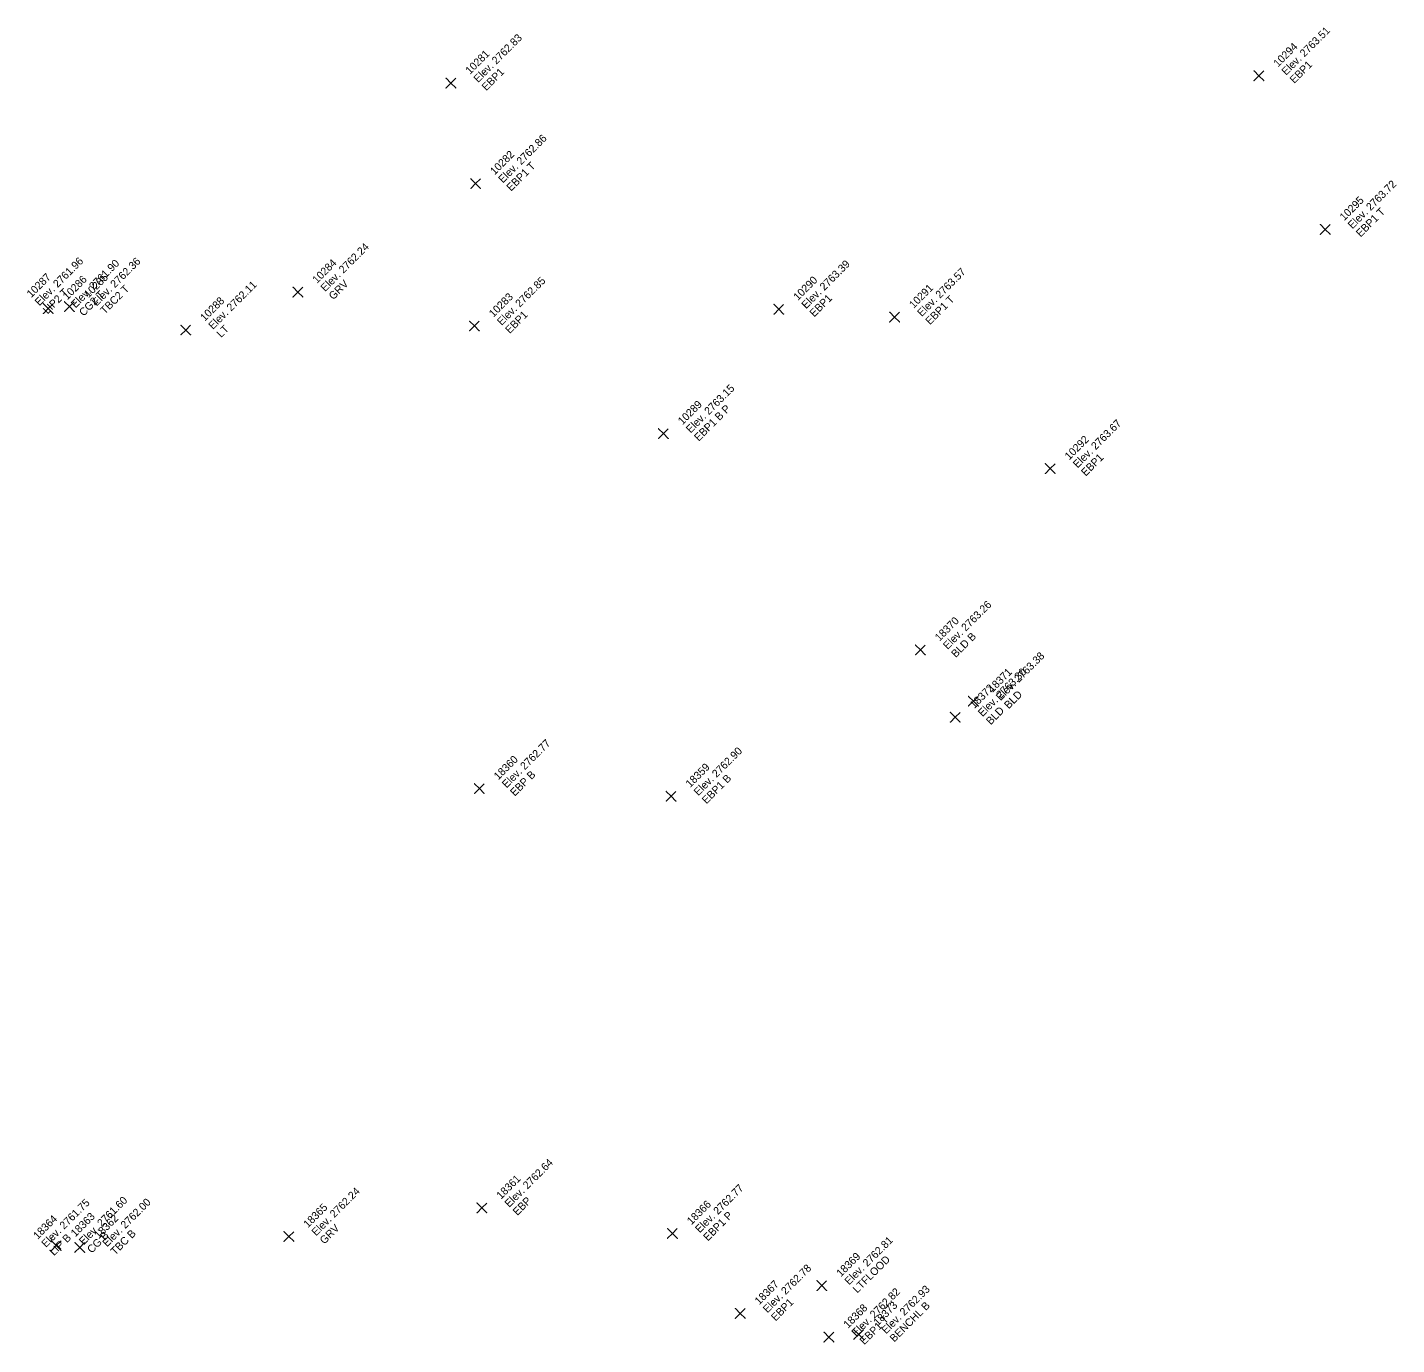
# Model space of a CAD drawing. Extents: x 2493999 to 2503109, y 700767 to 706646.
# Drawn here: x 2502305.4 to 2502348.06, y 701232.19 to 701273.23 of the extents above; entities that cross this region are included whole.
import ezdxf

# ---------------------------------------------------------------- set-up
doc = ezdxf.new("R2010")
doc.units = 0
doc.layers.add('ALG_CL_BLUE_Horiz', color=7, linetype='Continuous')
doc.layers.add('DES_SURFACE_Existing-Ground', color=7, linetype='Continuous')

msp = doc.modelspace()

# ---------------------------------------------------------------- linework, layer by layer
at = {"layer": 'ALG_CL_BLUE_Horiz'}
for points in [[(2502343.772, 701271.726), (2502343.622, 701271.876), (2502343.772, 701271.726), (2502343.622, 701271.576), (2502343.772, 701271.726), (2502343.922, 701271.576), (2502343.772, 701271.726), (2502343.922, 701271.876)], [(2502318.599, 701271.499), (2502318.449, 701271.649), (2502318.599, 701271.499), (2502318.449, 701271.349), (2502318.599, 701271.499), (2502318.749, 701271.349), (2502318.599, 701271.499), (2502318.749, 701271.649)], [(2502319.37, 701268.366), (2502319.22, 701268.516), (2502319.37, 701268.366), (2502319.22, 701268.216), (2502319.37, 701268.366), (2502319.52, 701268.216), (2502319.37, 701268.366), (2502319.52, 701268.516)], [(2502345.837, 701266.939), (2502345.687, 701267.089), (2502345.837, 701266.939), (2502345.687, 701266.789), (2502345.837, 701266.939), (2502345.987, 701266.789), (2502345.837, 701266.939), (2502345.987, 701267.089)], [(2502313.833, 701264.985), (2502313.683, 701265.135), (2502313.833, 701264.985), (2502313.683, 701264.835), (2502313.833, 701264.985), (2502313.983, 701264.835), (2502313.833, 701264.985), (2502313.983, 701265.135)], [(2502306.054, 701264.473), (2502305.904, 701264.623), (2502306.054, 701264.473), (2502305.904, 701264.323), (2502306.054, 701264.473), (2502306.204, 701264.323), (2502306.054, 701264.473), (2502306.204, 701264.623)], [(2502306.715, 701264.534), (2502306.565, 701264.684), (2502306.715, 701264.534), (2502306.565, 701264.384), (2502306.715, 701264.534), (2502306.865, 701264.384), (2502306.715, 701264.534), (2502306.865, 701264.684)], [(2502328.815, 701264.451), (2502328.665, 701264.601), (2502328.815, 701264.451), (2502328.665, 701264.301), (2502328.815, 701264.451), (2502328.965, 701264.301), (2502328.815, 701264.451), (2502328.965, 701264.601)], [(2502332.421, 701264.206), (2502332.271, 701264.356), (2502332.421, 701264.206), (2502332.271, 701264.056), (2502332.421, 701264.206), (2502332.571, 701264.056), (2502332.421, 701264.206), (2502332.571, 701264.356)], [(2502310.337, 701263.805), (2502310.187, 701263.955), (2502310.337, 701263.805), (2502310.187, 701263.655), (2502310.337, 701263.805), (2502310.487, 701263.655), (2502310.337, 701263.805), (2502310.487, 701263.955)], [(2502319.331, 701263.93), (2502319.181, 701264.08), (2502319.331, 701263.93), (2502319.181, 701263.78), (2502319.331, 701263.93), (2502319.481, 701263.78), (2502319.331, 701263.93), (2502319.481, 701264.08)], [(2502325.219, 701260.578), (2502325.069, 701260.728), (2502325.219, 701260.578), (2502325.069, 701260.428), (2502325.219, 701260.578), (2502325.369, 701260.428), (2502325.219, 701260.578), (2502325.369, 701260.728)], [(2502337.27, 701259.486), (2502337.12, 701259.636), (2502337.27, 701259.486), (2502337.12, 701259.336), (2502337.27, 701259.486), (2502337.42, 701259.336), (2502337.27, 701259.486), (2502337.42, 701259.636)], [(2502333.225, 701253.836), (2502333.075, 701253.986), (2502333.225, 701253.836), (2502333.075, 701253.686), (2502333.225, 701253.836), (2502333.375, 701253.686), (2502333.225, 701253.836), (2502333.375, 701253.986)], [(2502334.876, 701252.24), (2502334.726, 701252.39), (2502334.876, 701252.24), (2502334.726, 701252.09), (2502334.876, 701252.24), (2502335.026, 701252.09), (2502334.876, 701252.24), (2502335.026, 701252.39)], [(2502334.312, 701251.741), (2502334.162, 701251.891), (2502334.312, 701251.741), (2502334.162, 701251.591), (2502334.312, 701251.741), (2502334.462, 701251.591), (2502334.312, 701251.741), (2502334.462, 701251.891)], [(2502319.485, 701249.516), (2502319.335, 701249.666), (2502319.485, 701249.516), (2502319.335, 701249.366), (2502319.485, 701249.516), (2502319.635, 701249.366), (2502319.485, 701249.516), (2502319.635, 701249.666)], [(2502325.459, 701249.277), (2502325.309, 701249.427), (2502325.459, 701249.277), (2502325.309, 701249.127), (2502325.459, 701249.277), (2502325.609, 701249.127), (2502325.459, 701249.277), (2502325.609, 701249.427)], [(2502319.566, 701236.451), (2502319.416, 701236.601), (2502319.566, 701236.451), (2502319.416, 701236.301), (2502319.566, 701236.451), (2502319.716, 701236.301), (2502319.566, 701236.451), (2502319.716, 701236.601)], [(2502313.552, 701235.56), (2502313.402, 701235.71), (2502313.552, 701235.56), (2502313.402, 701235.41), (2502313.552, 701235.56), (2502313.702, 701235.41), (2502313.552, 701235.56), (2502313.702, 701235.71)], [(2502325.501, 701235.654), (2502325.351, 701235.804), (2502325.501, 701235.654), (2502325.351, 701235.504), (2502325.501, 701235.654), (2502325.651, 701235.504), (2502325.501, 701235.654), (2502325.651, 701235.804)], [(2502306.305, 701235.276), (2502306.155, 701235.426), (2502306.305, 701235.276), (2502306.155, 701235.126), (2502306.305, 701235.276), (2502306.455, 701235.126), (2502306.305, 701235.276), (2502306.455, 701235.426)], [(2502307.035, 701235.219), (2502306.885, 701235.369), (2502307.035, 701235.219), (2502306.885, 701235.069), (2502307.035, 701235.219), (2502307.185, 701235.069), (2502307.035, 701235.219), (2502307.185, 701235.369)], [(2502330.155, 701234.031), (2502330.005, 701234.181), (2502330.155, 701234.031), (2502330.005, 701233.881), (2502330.155, 701234.031), (2502330.305, 701233.881), (2502330.155, 701234.031), (2502330.305, 701234.181)], [(2502327.612, 701233.162), (2502327.462, 701233.312), (2502327.612, 701233.162), (2502327.462, 701233.012), (2502327.612, 701233.162), (2502327.762, 701233.012), (2502327.612, 701233.162), (2502327.762, 701233.312)], [(2502330.376, 701232.427), (2502330.226, 701232.577), (2502330.376, 701232.427), (2502330.226, 701232.277), (2502330.376, 701232.427), (2502330.526, 701232.277), (2502330.376, 701232.427), (2502330.526, 701232.577)], [(2502331.307, 701232.506), (2502331.157, 701232.656), (2502331.307, 701232.506), (2502331.157, 701232.356), (2502331.307, 701232.506), (2502331.457, 701232.356), (2502331.307, 701232.506), (2502331.457, 701232.656)]]:
    msp.add_lwpolyline(points, dxfattribs=at)

# ---------------------------------------------------------------- texts
at = {"layer": 'DES_SURFACE_Existing-Ground'}
for s, p in [('Elev. 2763.51', (2502344.621, 701271.726)), ('Elev. 2762.83', (2502319.448, 701271.499)), ('10294', (2502344.366, 701271.981)), ('10281', (2502319.193, 701271.754)), ('EBP1', (2502319.702, 701271.244)), ('EBP1', (2502344.875, 701271.471)), ('Elev. 2762.86', (2502320.219, 701268.366)), ('10282', (2502319.964, 701268.621)), ('EBP1 T', (2502320.473, 701268.111)), ('Elev. 2763.72', (2502346.686, 701266.939)), ('10295', (2502346.431, 701267.194)), ('EBP1 T', (2502346.94, 701266.684)), ('Elev. 2762.24', (2502314.682, 701264.985)), ('Elev. 2761.96', (2502305.78, 701264.542)), ('Elev. 2761.90', (2502306.903, 701264.473)), ('Elev. 2762.36', (2502307.564, 701264.534)), ('10284', (2502314.427, 701265.24)), ('Elev. 2763.39', (2502329.664, 701264.451)), ('10287', (2502305.525, 701264.797)), ('10286', (2502306.648, 701264.728)), ('10285', (2502307.309, 701264.789)), ('GRV', (2502314.936, 701264.73)), ('Elev. 2762.85', (2502320.18, 701263.93)), ('10290', (2502329.409, 701264.706)), ('Elev. 2763.57', (2502333.27, 701264.206)), ('LIP2 T', (2502306.034, 701264.287)), ('CG2 T', (2502307.157, 701264.218)), ('TBC2 T', (2502307.818, 701264.279)), ('Elev. 2762.11', (2502311.186, 701263.805)), ('10291', (2502333.015, 701264.461)), ('10288', (2502310.931, 701264.06)), ('10283', (2502319.925, 701264.185)), ('EBP1', (2502329.918, 701264.196)), ('EBP1 T', (2502333.524, 701263.951)), ('EBP1', (2502320.434, 701263.675)), ('LT', (2502311.44, 701263.55)), ('Elev. 2763.15', (2502326.068, 701260.578)), ('10289', (2502325.813, 701260.833)), ('EBP1 B P', (2502326.322, 701260.323)), ('Elev. 2763.67', (2502338.119, 701259.486)), ('10292', (2502337.864, 701259.741)), ('EBP1', (2502338.373, 701259.231)), ('Elev. 2763.26', (2502334.074, 701253.836)), ('18370', (2502333.819, 701254.091)), ('BLD B', (2502334.328, 701253.581)), ('Elev. 2763.38', (2502335.725, 701252.24)), ('Elev. 2763.30', (2502335.161, 701251.741)), ('18371', (2502335.47, 701252.495)), ('18372', (2502334.906, 701251.996)), ('BLD', (2502335.979, 701251.985)), ('BLD', (2502335.415, 701251.486)), ('Elev. 2762.77', (2502320.334, 701249.516)), ('18360', (2502320.079, 701249.771)), ('Elev. 2762.90', (2502326.308, 701249.277)), ('EBP B', (2502320.588, 701249.261)), ('18359', (2502326.053, 701249.532)), ('EBP1 B', (2502326.562, 701249.022)), ('Elev. 2762.64', (2502320.415, 701236.451)), ('18361', (2502320.16, 701236.706)), ('Elev. 2761.60', (2502307.154, 701235.276)), ('Elev. 2762.24', (2502314.401, 701235.56)), ('Elev. 2762.77', (2502326.35, 701235.654)), ('Elev. 2761.75', (2502305.981, 701235.2)), ('Elev. 2762.00', (2502307.884, 701235.219)), ('18365', (2502314.146, 701235.815)), ('EBP', (2502320.669, 701236.196)), ('18366', (2502326.095, 701235.909)), ('18364', (2502305.726, 701235.455)), ('18363', (2502306.899, 701235.531)), ('18362', (2502307.629, 701235.474)), ('GRV', (2502314.655, 701235.305)), ('EBP1 P', (2502326.604, 701235.399)), ('LIP B', (2502306.235, 701234.945)), ('CG B', (2502307.408, 701235.021)), ('TBC B', (2502308.138, 701234.964)), ('Elev. 2762.81', (2502331.004, 701234.031)), ('Elev. 2762.78', (2502328.461, 701233.162)), ('18369', (2502330.749, 701234.286)), ('LTFLOOD', (2502331.258, 701233.776)), ('18367', (2502328.206, 701233.417)), ('Elev. 2762.82', (2502331.225, 701232.427)), ('Elev. 2762.93', (2502332.156, 701232.506)), ('EBP1', (2502328.715, 701232.907)), ('18368', (2502330.97, 701232.682)), ('18373', (2502331.901, 701232.761)), ('BENCHL B', (2502332.41, 701232.251)), ('EBP1 T', (2502331.479, 701232.172))]:
    msp.add_text(s, height=0.24, rotation=45, dxfattribs=at).set_placement(p)

doc.saveas('drawing.dxf')
